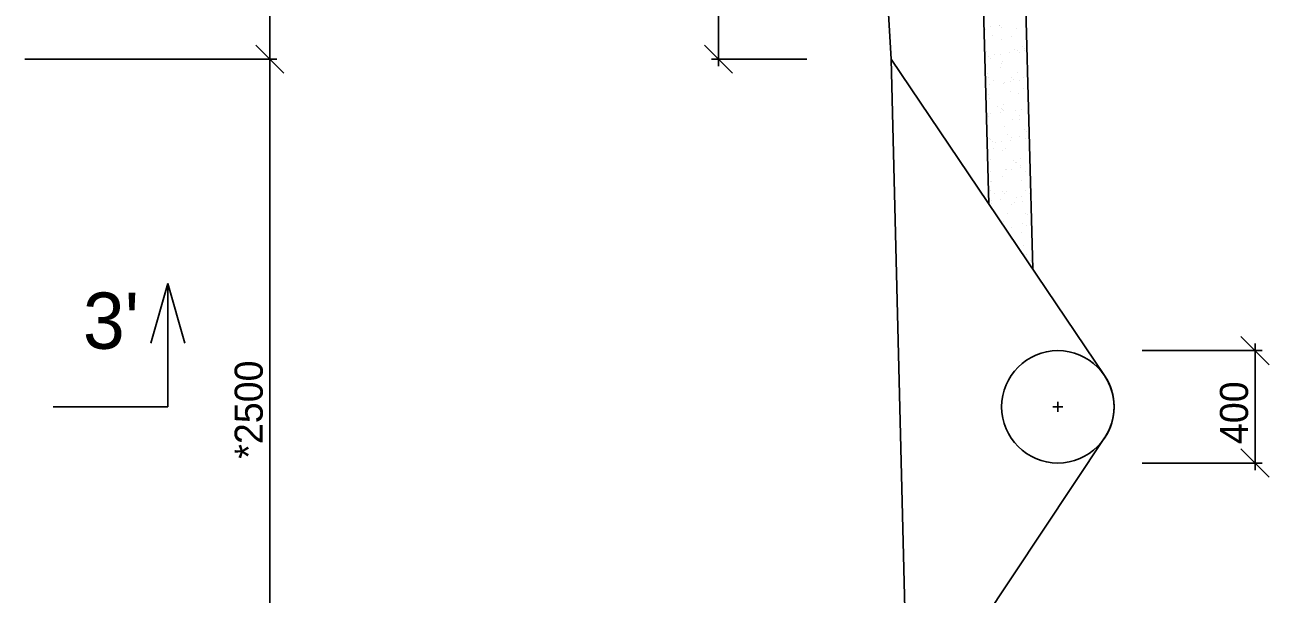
# Model space of a CAD drawing. Extents: x -2363 to 18637, y 14070 to 28920.
# Drawn here: x 9940 to 14366, y 19936 to 21961 of the extents above; entities that cross this region are included whole.
import ezdxf

# ---------------------------------------------------------------- set-up
doc = ezdxf.new("R2010")
doc.units = 0
for name, color, linetype in [('KÓTY', 7, 'Continuous'), ('OBRYS', 7, 'Continuous'), ('SJEZD', 7, 'Continuous'), ('ŠRAFY', 7, 'Continuous')]:
    doc.layers.add(name, color=color, linetype=linetype)

# ---------------------------------------------------------------- blocks, each defined once
blk = doc.blocks.new('_ARCHTICK')
blk.add_lwpolyline([(-0.5, -0.5), (0.5, 0.5)])

msp = doc.modelspace()

# ---------------------------------------------------------------- linework, layer by layer
at = {"layer": 'KÓTY'}
for p, q in [((10811.4, 21814.7), (10811.4, 22364.7)), ((12407.6, 21814.7), (12407.6, 22364.7)), ((10761.4, 21889.7), (10861.4, 21789.7)), ((10861.4, 21789.7), (10761.4, 21889.7)), ((9940.2, 21839.7), (10836.4, 21839.7)), ((10090.2, 21839.7), (10836.4, 21839.7)), ((10811.4, 19294.4), (10811.4, 21864.7)), ((12721.9, 21839.7), (12382.6, 21839.7)), ((10448.7, 21041.5), (10388.7, 20829)), ((10448.7, 21041.5), (10508.7, 20829)), ((10448.7, 20602.2), (10448.7, 21041.5)), ((14316.4, 20377.2), (14316.4, 20827.2)), ((13914.8, 20802.2), (14341.4, 20802.2)), ((10040.7, 20602.2), (10448.7, 20602.2)), ((13914.8, 20402.2), (14341.4, 20402.2))]:
    msp.add_line(p, q, dxfattribs=at)
at = {"layer": 'OBRYS'}
for p, q in [((13525.3, 21092.9), (13387.1, 26258.2)), ((13021.9, 21839.7), (12991.9, 22339.7)), ((13781.2, 20713.2), (13021.9, 21839.7)), ((13081.5, 19441.7), (13781.2, 20491.3))]:
    msp.add_line(p, q, dxfattribs=at)
msp.add_arc((13614.8, 20602.2), 200, 326.3099, 33.9818, dxfattribs=at)
at = {"layer": 'SJEZD'}
for p, q in [((13387.1, 26258.2), (13525.3, 21092.9)), ((13251.6, 25715.5), (13369.1, 21324.7)), ((12991.9, 22339.7), (13021.9, 21839.7)), ((13021.9, 21839.7), (13780.7, 20714)), ((13021.9, 21839.7), (13081.5, 19441.7)), ((13632.2, 20602.2), (13597.5, 20602.2)), ((13614.8, 20619.6), (13614.8, 20584.9)), ((13781.2, 20491.3), (13081.5, 19441.7))]:
    msp.add_line(p, q, dxfattribs=at)
msp.add_circle((13614.8, 20602.2), 200, dxfattribs=at)
msp.add_arc((13614.8, 20602.2), 200, 326.3099, 33.6901, dxfattribs=at)
at = {"layer": 'ŠRAFY'}
for p, q in [((13373.6, 21956), (13373.6, 21956)), ((13406.1, 21960.3), (13406.1, 21960.3)), ((13407.3, 21958.1), (13407.3, 21958.1)), ((13352.8, 21953.3), (13352.8, 21953.3)), ((13359.2, 21943.8), (13359.2, 21943.8)), ((13382.3, 21923.6), (13382.3, 21923.6)), ((13414.7, 21951.4), (13414.7, 21951.4)), ((13449.5, 21919.5), (13449.5, 21919.5)), ((13467.3, 21947.7), (13467.3, 21947.7)), ((13361.8, 21866.8), (13361.8, 21866.8)), ((13415.7, 21908.2), (13415.7, 21908.2)), ((13461.6, 21873.1), (13461.6, 21873.1)), ((13469.8, 21870.7), (13469.8, 21870.7)), ((13489.3, 21883), (13489.3, 21883)), ((13496.7, 21876.2), (13496.7, 21876.2)), ((13497.3, 21868.8), (13497.3, 21868.8)), ((13369.1, 21847.9), (13369.1, 21847.9)), ((13376.4, 21841.1), (13376.4, 21841.1)), ((13389.6, 21854.6), (13389.6, 21854.6)), ((13410.5, 21857.3), (13410.5, 21857.3)), ((13414.6, 21823.5), (13414.6, 21823.5)), ((13418.2, 21831.1), (13418.2, 21831.1)), ((13443, 21861.6), (13443, 21861.6)), ((13478.5, 21862.4), (13478.5, 21862.4)), ((13364.3, 21789.7), (13364.3, 21789.7)), ((13411.2, 21809.2), (13411.2, 21809.2)), ((13472.3, 21793.6), (13472.3, 21793.6)), ((13369.4, 21772.7), (13369.4, 21772.7)), ((13372.2, 21748.7), (13372.2, 21748.7)), ((13386.2, 21762), (13386.2, 21762)), ((13420.7, 21754), (13420.7, 21754)), ((13426.5, 21755.9), (13426.5, 21755.9)), ((13447.3, 21758.6), (13447.3, 21758.6)), ((13451, 21772.8), (13451, 21772.8)), ((13458.4, 21766), (13458.4, 21766)), ((13479.9, 21762.9), (13479.9, 21762.9)), ((13493.2, 21734.1), (13493.2, 21734.1)), ((13493.9, 21773), (13493.9, 21773)), ((13366.8, 21712.6), (13366.8, 21712.6)), ((13373, 21699), (13373, 21699)), ((13446.9, 21723.3), (13446.9, 21723.3)), ((13474.8, 21716.5), (13474.8, 21716.5)), ((13376.5, 21645.7), (13376.5, 21645.7)), ((13401.7, 21672.6), (13401.7, 21672.6)), ((13409.1, 21650), (13409.1, 21650)), ((13412.8, 21662.5), (13412.8, 21662.5)), ((13418.5, 21661.8), (13418.5, 21661.8)), ((13420.2, 21655.8), (13420.2, 21655.8)), ((13423.3, 21677), (13423.3, 21677)), ((13463.4, 21657.2), (13463.4, 21657.2)), ((13484.2, 21659.9), (13484.2, 21659.9)), ((13369.3, 21635.6), (13369.3, 21635.6)), ((13455, 21623.9), (13455, 21623.9)), ((13477.3, 21639.4), (13477.3, 21639.4)), ((13479.3, 21623.1), (13479.3, 21623.1)), ((13371.8, 21558.5), (13371.8, 21558.5)), ((13425.8, 21599.9), (13425.8, 21599.9)), ((13434, 21572.4), (13434, 21572.4)), ((13450.8, 21561.7), (13450.8, 21561.7)), ((13479.9, 21562.4), (13479.9, 21562.4)), ((13494.8, 21587.4), (13494.8, 21587.4)), ((13500.3, 21558.5), (13500.3, 21558.5)), ((13502.1, 21580.6), (13502.1, 21580.6)), ((13374.5, 21552.3), (13374.5, 21552.3)), ((13381.9, 21545.5), (13381.9, 21545.5)), ((13387, 21522.7), (13387, 21522.7)), ((13392.6, 21544.3), (13392.6, 21544.3)), ((13413.4, 21547), (13413.4, 21547)), ((13416.7, 21513.7), (13416.7, 21513.7)), ((13428.3, 21522.8), (13428.3, 21522.8)), ((13445.9, 21551.3), (13445.9, 21551.3)), ((13511.6, 21523), (13511.6, 21523)), ((13374.4, 21481.4), (13374.4, 21481.4)), ((13456.5, 21477.2), (13456.5, 21477.2)), ((13463.9, 21470.4), (13463.9, 21470.4)), ((13466.3, 21472.2), (13466.3, 21472.2)), ((13482.4, 21485.3), (13482.4, 21485.3)), ((13375.2, 21438.4), (13375.2, 21438.4)), ((13429.5, 21445.6), (13429.5, 21445.6)), ((13430.8, 21445.7), (13430.8, 21445.7)), ((13450.3, 21448.3), (13450.3, 21448.3)), ((13482.8, 21452.6), (13482.8, 21452.6)), ((13483.1, 21461.5), (13483.1, 21461.5)), ((13498.7, 21438.5), (13498.7, 21438.5)), ((13376.9, 21404.3), (13376.9, 21404.3)), ((13378.4, 21403.4), (13378.4, 21403.4)), ((13419.3, 21422.6), (13419.3, 21422.6)), ((13484.9, 21408.2), (13484.9, 21408.2)), ((13374, 21371.8), (13374, 21371.8)), ((13379.5, 21335.4), (13379.5, 21335.4)), ((13390.9, 21361.1), (13390.9, 21361.1)), ((13412, 21339.7), (13412, 21339.7)), ((13418.3, 21366.9), (13418.3, 21366.9)), ((13425.6, 21360.2), (13425.6, 21360.2)), ((13433.3, 21368.7), (13433.3, 21368.7)), ((13466.4, 21346.9), (13466.4, 21346.9)), ((13487.2, 21349.6), (13487.2, 21349.6)), ((13498.6, 21372.1), (13498.6, 21372.1)), ((13515.4, 21361.3), (13515.4, 21361.3)), ((13379.4, 21327.3), (13379.4, 21327.3)), ((13435.9, 21291.6), (13435.9, 21291.6)), ((13451.6, 21322.4), (13451.6, 21322.4)), ((13460.4, 21328.3), (13460.4, 21328.3)), ((13487.4, 21331.2), (13487.4, 21331.2)), ((13500.2, 21291.8), (13500.2, 21291.8)), ((13406.3, 21271.7), (13406.3, 21271.7)), ((13423.2, 21260.9), (13423.2, 21260.9)), ((13489.9, 21254.1), (13489.9, 21254.1)), ((13503.2, 21248.1), (13503.2, 21248.1)), ((13507.6, 21285.1), (13507.6, 21285.1)), ((13448.9, 21241), (13448.9, 21241)), ((13483.9, 21222.3), (13483.9, 21222.3)), ((13492.5, 21177), (13492.5, 21177)), ((13504.2, 21142.9), (13504.2, 21142.9)), ((13516.2, 21122.1), (13516.2, 21122.1))]:
    msp.add_line(p, q, dxfattribs=at)

# ---------------------------------------------------------------- block references
at = {"layer": 'KÓTY', "xscale": 100, "yscale": 100}
for p, rotation in [((10811.4, 21839.7), -90.00000000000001), ((10811.4, 21839.7), 90), ((12407.6, 21839.7), -90.00000000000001), ((14316.4, 20802.2), 90), ((14316.4, 20402.2), -90.00000000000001)]:
    msp.add_blockref('_ARCHTICK', p, dxfattribs=dict(at, rotation=rotation))

# ---------------------------------------------------------------- texts
at = {"layer": 'KÓTY'}
msp.add_text("3'", height=200, dxfattribs=at).set_placement((10146.6, 20808.8))
for s, p in [('*2500', (10786.4, 20417.5)), ('400', (14291.4, 20469.6))]:
    msp.add_text(s, height=100, rotation=90, dxfattribs=at).set_placement(p)

doc.saveas('drawing.dxf')
